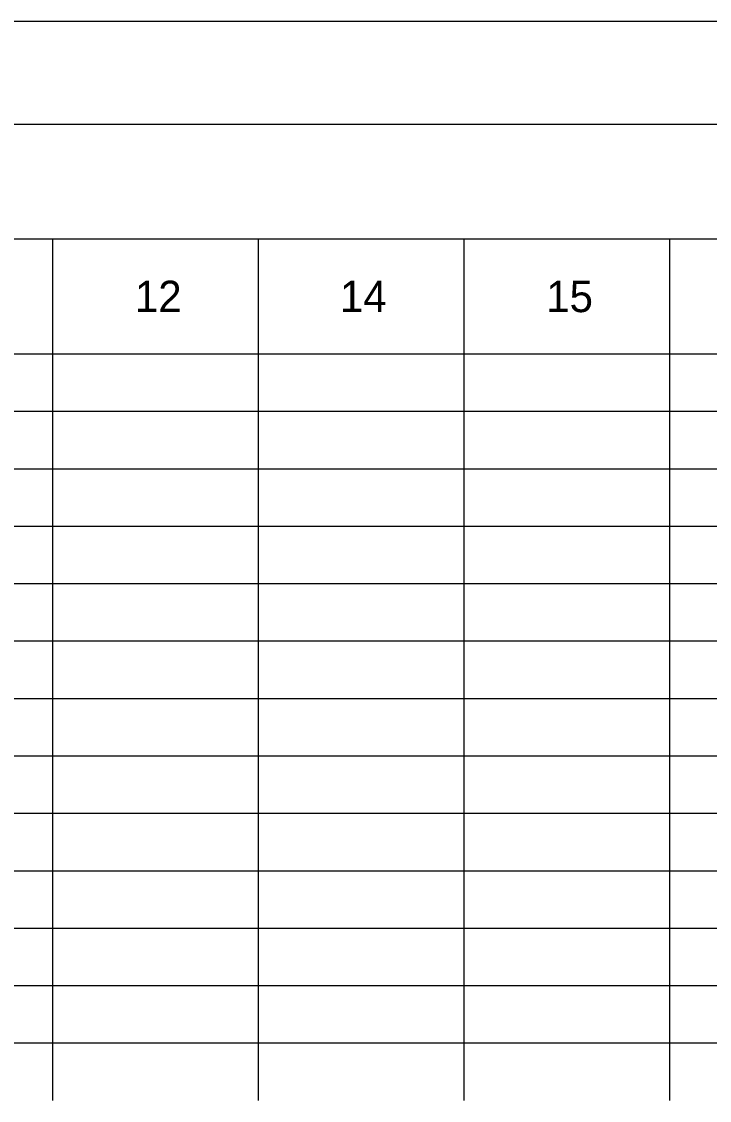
# Model space of a CAD drawing. Extents: x 0 to 34, y 0 to 22.
# Drawn here: x 3.35 to 6.71, y 16.74 to 22 of the extents above; entities that cross this region are included whole.
import ezdxf

# ---------------------------------------------------------------- set-up
doc = ezdxf.new("R2010")
doc.units = 0
for name, color, linetype in [('SH_Border', 7, 'Continuous'), ('SH_Cut_Line', 7, 'Continuous'), ('SH_Text', 7, 'Continuous')]:
    doc.layers.add(name, color=color, linetype=linetype)

msp = doc.modelspace()

# ---------------------------------------------------------------- linework, layer by layer
at = {"layer": 'SH_Border'}
msp.add_lwpolyline([(1.5, 21.5), (33.5, 21.5), (33.5, 0.5), (1.5, 0.5)], close=True, dxfattribs=at)
at = {"layer": 'SH_Cut_Line'}
msp.add_lwpolyline([(0, 0), (34, 0), (34, 22), (0, 22)], close=True, dxfattribs=at)
at = {"layer": 'SH_Text'}
for p, q in [((1.5, 21.5), (6.5133, 21.5)), ((6.5133, 21.5), (7.516, 21.5)), ((1.5, 20.94), (6.5133, 20.94)), ((3.5053, 20.94), (3.5053, 20.66)), ((4.508, 20.94), (4.508, 20.66)), ((5.5106, 20.94), (5.5106, 20.66)), ((6.5133, 20.94), (7.516, 20.94)), ((6.5133, 20.94), (6.5133, 20.66)), ((3.5053, 20.66), (3.5053, 20.38)), ((4.508, 20.66), (4.508, 20.38)), ((5.5106, 20.66), (5.5106, 20.38)), ((6.5133, 20.66), (6.5133, 20.38)), ((1.5, 20.38), (6.5133, 20.38)), ((3.5053, 20.38), (3.5053, 20.1)), ((4.508, 20.38), (4.508, 20.1)), ((5.5106, 20.38), (5.5106, 20.1)), ((6.5133, 20.38), (7.516, 20.38)), ((6.5133, 20.38), (6.5133, 20.1)), ((1.5, 20.1), (6.5133, 20.1)), ((3.5053, 20.1), (3.5053, 18.6999)), ((4.508, 20.1), (4.508, 18.6999)), ((5.5106, 20.1), (5.5106, 18.6999)), ((6.5133, 20.1), (7.516, 20.1)), ((6.5133, 20.1), (6.5133, 18.6999)), ((1.5, 19.82), (6.5133, 19.82)), ((6.5133, 19.82), (7.516, 19.82)), ((1.5, 19.5399), (6.5133, 19.5399)), ((6.5133, 19.5399), (7.516, 19.5399)), ((1.5, 19.2599), (6.5133, 19.2599)), ((6.5133, 19.2599), (7.516, 19.2599)), ((1.5, 18.9799), (6.5133, 18.9799)), ((6.5133, 18.9799), (7.516, 18.9799)), ((1.5, 18.6999), (6.5133, 18.6999)), ((3.5053, 18.6999), (3.5053, 18.1399)), ((4.508, 18.6999), (4.508, 18.1399)), ((5.5106, 18.6999), (5.5106, 18.1399)), ((6.5133, 18.6999), (7.516, 18.6999)), ((6.5133, 18.6999), (6.5133, 18.1399)), ((1.5, 18.4199), (6.5133, 18.4199)), ((6.5133, 18.4199), (7.516, 18.4199)), ((1.5, 18.1399), (6.5133, 18.1399)), ((3.5053, 18.1399), (3.5053, 17.8599)), ((4.508, 18.1399), (4.508, 17.8599)), ((5.5106, 18.1399), (5.5106, 17.8599)), ((6.5133, 18.1399), (7.516, 18.1399)), ((6.5133, 18.1399), (6.5133, 17.8599)), ((1.5, 17.8599), (6.5133, 17.8599)), ((3.5053, 17.8599), (3.5053, 17.5799)), ((4.508, 17.8599), (4.508, 17.5799)), ((5.5106, 17.8599), (5.5106, 17.5799)), ((6.5133, 17.8599), (7.516, 17.8599)), ((6.5133, 17.8599), (6.5133, 17.5799)), ((1.5, 17.5799), (6.5133, 17.5799)), ((3.5053, 17.5799), (3.5053, 17.2999)), ((4.508, 17.5799), (4.508, 17.2999)), ((5.5106, 17.5799), (5.5106, 17.2999)), ((6.5133, 17.5799), (7.516, 17.5799)), ((6.5133, 17.5799), (6.5133, 17.2999)), ((1.5, 17.2999), (6.5133, 17.2999)), ((3.5053, 17.2999), (3.5053, 17.0199)), ((4.508, 17.2999), (4.508, 17.0199)), ((5.5106, 17.2999), (5.5106, 17.0199)), ((6.5133, 17.2999), (7.516, 17.2999)), ((6.5133, 17.2999), (6.5133, 17.0199)), ((1.5, 17.0199), (6.5133, 17.0199)), ((3.5053, 17.0199), (3.5053, 16.7399)), ((4.508, 17.0199), (4.508, 16.7399)), ((5.5106, 17.0199), (5.5106, 16.7399)), ((6.5133, 17.0199), (7.516, 17.0199)), ((6.5133, 17.0199), (6.5133, 16.7399))]:
    msp.add_line(p, q, dxfattribs=at)

# ---------------------------------------------------------------- texts
for s, p in [('12', (3.9063, 20.5833)), ('14', (4.9061, 20.5833)), ('15', (5.9119, 20.5833))]:
    msp.add_text(s, height=0.15334, dxfattribs=at).set_placement(p)

doc.saveas('drawing.dxf')
